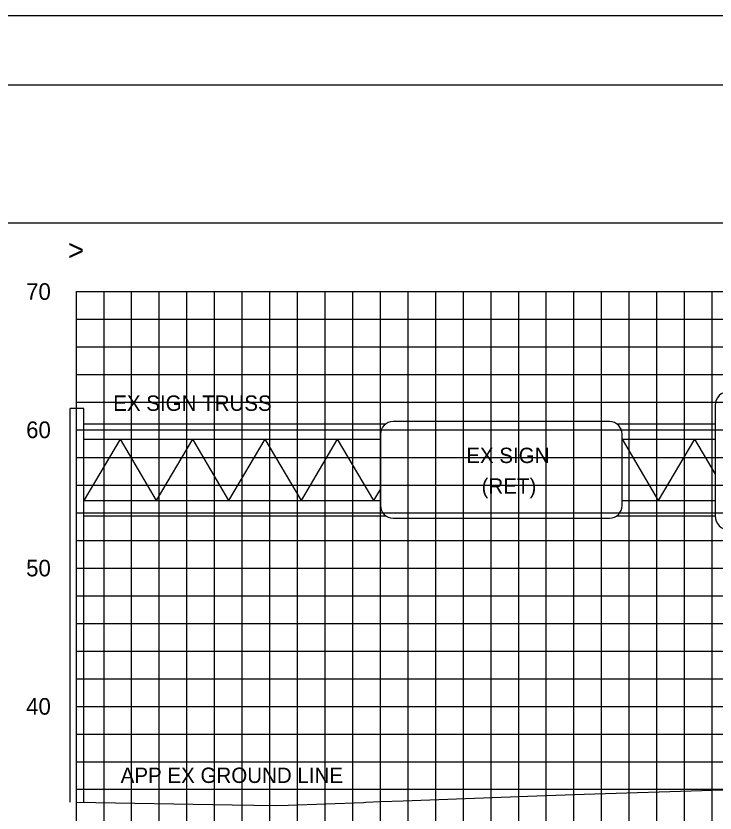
# Model space of a CAD drawing. Extents: x 1797809 to 2198143, y 249608 to 1237864.
# Drawn here: x 2194693.3 to 2194743.9, y 1237280.4 to 1237338 of the extents above; entities that cross this region are included whole.
import ezdxf

# ---------------------------------------------------------------- set-up
doc = ezdxf.new("R2010")
doc.units = 0
for name, color, linetype in [('3', 7, 'Continuous'), ('31', 7, 'Continuous'), ('60', 7, 'Continuous'), ('DESIGN - SHEET - Light Grid', 7, 'Continuous'), ('GSCOLORFILL', 7, 'Continuous'), ('GSDIMS', 7, 'Continuous'), ('GSSHT', 7, 'Continuous'), ('Level 45', 7, 'Continuous'), ('Level 55', 7, 'Continuous')]:
    doc.layers.add(name, color=color, linetype=linetype)

msp = doc.modelspace()

# ---------------------------------------------------------------- linework, layer by layer
at = {"layer": '3'}
for p, q in [((2194698.227, 1237309.648), (2194697.227, 1237309.648)), ((2194697.227, 1237281.177), (2194697.227, 1237309.648)), ((2194698.227, 1237281.16), (2194698.227, 1237309.648))]:
    msp.add_line(p, q, dxfattribs=at)
at = {"layer": '60'}
msp.add_line((2194697.688, 1237258.106), (2194697.688, 1237318.106), dxfattribs=at)
at = {"layer": 'DESIGN - SHEET - Light Grid'}
msp.add_lwpolyline([(2194697.688, 1237281.169), (2194708.963, 1237280.979), (2194712.089, 1237280.929), (2194713.022, 1237280.964), (2194718.467, 1237281.16), (2194718.636, 1237281.168), (2194719.717, 1237281.229), (2194721.327, 1237281.286), (2194731.003, 1237281.638), (2194734.434, 1237281.747), (2194743.707, 1237282.046), (2194752.078, 1237282.294)], dxfattribs=at)
at = {"layer": 'GSCOLORFILL'}
msp.add_line((2194743.895, 1237309.869), (2194743.895, 1237301.877), dxfattribs=at)
msp.add_lwpolyline([(2194525.191, 1237123.036), (2194847.691, 1237123.036), (2194847.691, 1237333.036), (2194525.191, 1237333.036)], close=True, dxfattribs=at)
for centre, start, end in [((2194744.894, 1237309.869), 90, 180), ((2194744.894, 1237301.877), 180, 270)]:
    msp.add_arc(centre, 0.999, start, end, dxfattribs=at)
at = {"layer": 'GSDIMS'}
for p, q in [((2194698.227, 1237308.538), (2194720.078, 1237308.538)), ((2194736.255, 1237308.704), (2194720.604, 1237308.704)), ((2194736.781, 1237308.538), (2194743.895, 1237308.538)), ((2194698.227, 1237307.427), (2194719.688, 1237307.427)), ((2194700.846, 1237307.427), (2194698.227, 1237302.987)), ((2194700.846, 1237307.427), (2194703.465, 1237302.987)), ((2194706.084, 1237307.427), (2194703.465, 1237302.987)), ((2194706.084, 1237307.427), (2194708.703, 1237302.987)), ((2194711.322, 1237307.427), (2194708.703, 1237302.987)), ((2194711.322, 1237307.427), (2194713.941, 1237302.987)), ((2194716.561, 1237307.427), (2194713.941, 1237302.987)), ((2194716.561, 1237307.427), (2194719.18, 1237302.987)), ((2194719.688, 1237307.788), (2194719.688, 1237302.627)), ((2194737.171, 1237302.627), (2194737.171, 1237307.788)), ((2194737.171, 1237307.427), (2194743.895, 1237307.427)), ((2194737.171, 1237307.427), (2194739.79, 1237302.987)), ((2194742.409, 1237307.427), (2194739.79, 1237302.987)), ((2194742.409, 1237307.427), (2194743.895, 1237304.907)), ((2194719.688, 1237303.849), (2194719.18, 1237302.987)), ((2194698.227, 1237302.987), (2194719.688, 1237302.987)), ((2194737.171, 1237302.987), (2194743.895, 1237302.987)), ((2194698.227, 1237301.877), (2194720.078, 1237301.877)), ((2194720.606, 1237301.711), (2194736.255, 1237301.711)), ((2194736.781, 1237301.877), (2194743.895, 1237301.877))]:
    msp.add_line(p, q, dxfattribs=at)
for centre, start, end in [((2194720.604, 1237307.788), 90, 180), ((2194736.255, 1237307.788), 0, 90), ((2194720.604, 1237302.627), 180, 270), ((2194736.255, 1237302.627), 270, 0)]:
    msp.add_arc(centre, 0.916, start, end, dxfattribs=at)
at = {"layer": 'GSSHT'}
for p, q in [((2194697.688, 1237318.106), (2194827.688, 1237318.106)), ((2194699.688, 1237258.106), (2194699.688, 1237318.106)), ((2194701.688, 1237258.106), (2194701.688, 1237318.106)), ((2194703.688, 1237258.106), (2194703.688, 1237318.106)), ((2194705.688, 1237258.106), (2194705.688, 1237318.106)), ((2194707.688, 1237258.106), (2194707.688, 1237318.106)), ((2194709.688, 1237258.106), (2194709.688, 1237318.106)), ((2194711.688, 1237258.106), (2194711.688, 1237318.106)), ((2194713.688, 1237258.106), (2194713.688, 1237318.106)), ((2194715.688, 1237258.106), (2194715.688, 1237318.106)), ((2194717.688, 1237258.106), (2194717.688, 1237318.106)), ((2194719.688, 1237258.106), (2194719.688, 1237318.106)), ((2194721.688, 1237258.106), (2194721.688, 1237318.106)), ((2194723.688, 1237258.106), (2194723.688, 1237318.106)), ((2194725.688, 1237258.106), (2194725.688, 1237318.106)), ((2194727.688, 1237258.106), (2194727.688, 1237318.106)), ((2194729.688, 1237258.106), (2194729.688, 1237318.106)), ((2194731.688, 1237258.106), (2194731.688, 1237318.106)), ((2194733.688, 1237258.106), (2194733.688, 1237318.106)), ((2194735.688, 1237258.106), (2194735.688, 1237318.106)), ((2194737.688, 1237258.106), (2194737.688, 1237318.106)), ((2194739.688, 1237258.106), (2194739.688, 1237318.106)), ((2194741.688, 1237258.106), (2194741.688, 1237318.106)), ((2194743.688, 1237258.106), (2194743.688, 1237318.106)), ((2194697.688, 1237316.106), (2194827.688, 1237316.106)), ((2194697.688, 1237314.106), (2194827.688, 1237314.106)), ((2194697.688, 1237312.106), (2194827.688, 1237312.106)), ((2194697.688, 1237310.106), (2194827.688, 1237310.106)), ((2194697.688, 1237308.106), (2194827.688, 1237308.106)), ((2194697.688, 1237306.106), (2194827.688, 1237306.106)), ((2194697.688, 1237304.106), (2194827.688, 1237304.106)), ((2194697.688, 1237302.106), (2194827.688, 1237302.106)), ((2194697.688, 1237300.106), (2194827.688, 1237300.106)), ((2194697.688, 1237298.106), (2194827.688, 1237298.106)), ((2194697.688, 1237296.106), (2194827.688, 1237296.106)), ((2194697.688, 1237294.106), (2194827.688, 1237294.106)), ((2194697.688, 1237292.106), (2194827.688, 1237292.106)), ((2194697.688, 1237290.106), (2194827.688, 1237290.106)), ((2194697.688, 1237288.106), (2194827.688, 1237288.106)), ((2194697.688, 1237286.106), (2194827.688, 1237286.106)), ((2194697.688, 1237284.106), (2194827.688, 1237284.106)), ((2194697.688, 1237282.106), (2194827.688, 1237282.106))]:
    msp.add_line(p, q, dxfattribs=at)
msp.add_lwpolyline([(2194512.691, 1237118.036), (2194852.691, 1237118.036), (2194852.691, 1237338.036), (2194512.691, 1237338.036)], close=True, dxfattribs=at)
at = {"layer": 'Level 45'}
msp.add_lwpolyline([(2194537.688, 1237133.046), (2194837.688, 1237133.046), (2194837.688, 1237323.046), (2194537.688, 1237323.046)], close=True, dxfattribs=at)

# ---------------------------------------------------------------- texts
at = {"layer": '31'}
for s, p in [('70', (2194694.054, 1237317.506)), ('60', (2194694.054, 1237307.506)), ('50', (2194694.054, 1237297.506)), ('40', (2194694.054, 1237287.506))]:
    msp.add_text(s, height=1.2, dxfattribs=at).set_placement(p)
at = {"layer": '60'}
msp.add_text('>', height=1.5, dxfattribs=at).set_placement((2194697.08, 1237320.356))
at = {"layer": 'Level 55'}
for s, height, p in [('EX SIGN TRUSS', 1.11046, (2194700.35, 1237309.478)), ('EX SIGN', 1.1105, (2194725.894, 1237305.702)), ('(RET)', 1.1105, (2194727.005, 1237303.481)), ('APP EX GROUND LINE', 1.11046, (2194700.891, 1237282.566))]:
    msp.add_text(s, height=height, dxfattribs=at).set_placement(p)

doc.saveas('drawing.dxf')
